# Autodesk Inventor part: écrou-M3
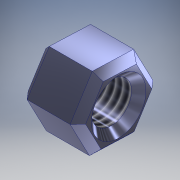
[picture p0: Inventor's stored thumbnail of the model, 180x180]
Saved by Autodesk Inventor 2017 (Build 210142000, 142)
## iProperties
Part Number: écrou-M3
Material: Générique
Document SubType Name: Modeling
Designer: Bruno
Density: 1 g/cm^3
Appearance: Chrome - Bleu poli
Author: Bruno
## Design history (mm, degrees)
sketch "Esquisse1"
  geometry: L1 (-1.541, -2.441)-(-2.885, 0.114); L2 (-2.885, 0.114)-(-1.344, 2.555); L3 (-1.344, 2.555)-(1.541, 2.441); L4 (1.541, 2.441)-(2.885, -0.114); L5 (2.885, -0.114)-(1.344, -2.555); L6 (1.344, -2.555)-(-1.541, -2.441); C1 r 1.4 at (0, 0); 2 further points
  constraints: 12 end point, 2 coincident, 1 centre point, 13 other
  dimensions: "d0" = 5 distance between parallel lines of L3 L6; "d1" = 2.8 diameter of C1
extrude "Extrusion1" new body sketch "Esquisse1" distance "d2" = 4; taper "d3" = 0 deg
chamfer "Chanfrein1" distance "d4" = 0.5; stored, may be unused: second distance "d5" = 2, angle "d6" = 45 deg
feature "Filetage1" dims "d7" = 10, "d8" = 0
chamfer "Chanfrein2" distance "d9" = 0.5; stored, may be unused: second distance "d10" = 2, angle "d11" = 45 deg
node "Solide1"
